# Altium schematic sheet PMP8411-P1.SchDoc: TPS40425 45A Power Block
size 431 x 279 mm; VersionControl_RevNumber: REV B; Date: Not shown in title block; ApprovedBy: Not shown in title block; CheckedBy: Not shown in title block; Author: Not shown in title block; CompanyName: Not shown in title block; DrawnBy: Tiger Zhou; Organization: Not shown in title block; Address1: Not shown in title block; Address2: Not shown in title block; Address3: Not shown in title block; Address4: Not shown in title block; DocumentNumber: 1; Revision: Use project parameter SCH_Rev; SheetNumber: 1; SheetTotal: 3; PageSetup: Record=PageOptions¦CenterHorizontal=True¦CenterVertical=True¦PrintScale=0.64¦XCorrection=1.00¦YCorrection=1.00¦PrintKind=0¦BorderSize=5000000¦LeftOffset=0¦BottomOffset=0¦Orientation=2¦PaperLength=1000¦PaperWidth=1000¦Scale=100¦PaperSource=15¦PrintQuality=600¦MediaType=1¦DitherType=10¦PrintScaleMode=1¦PaperKind=Letter
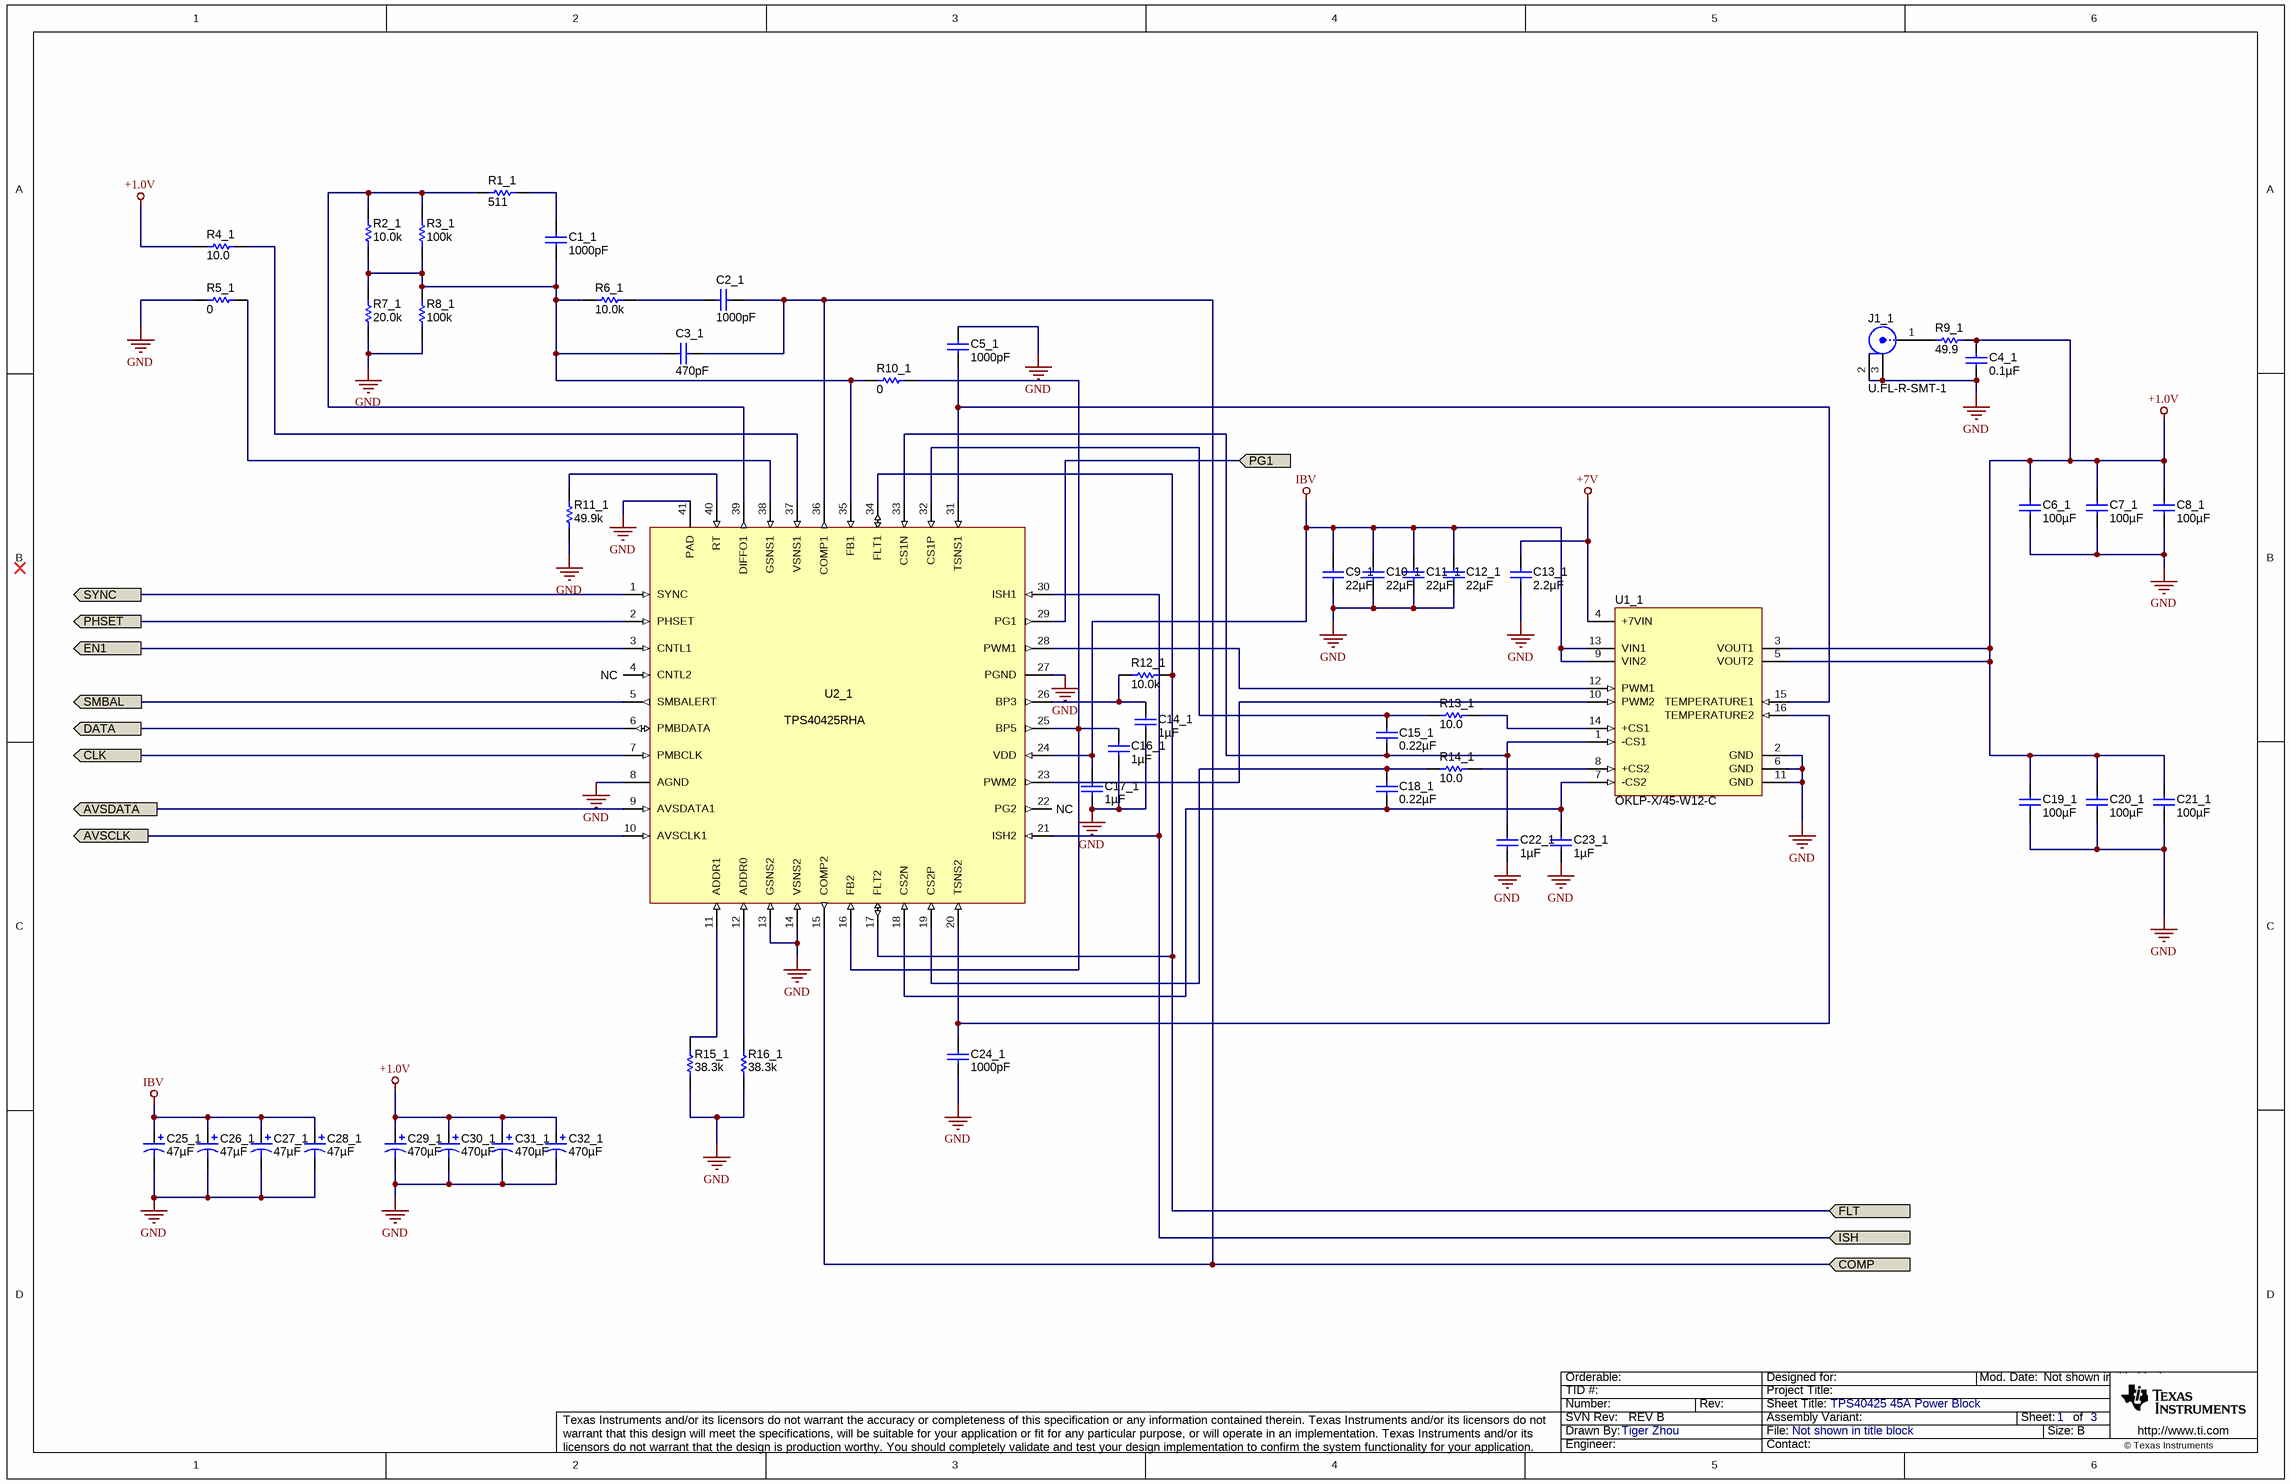
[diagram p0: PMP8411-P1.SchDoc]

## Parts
C1_1  ValueDisplayed: 1000pF  [0402S]  (hidden comment: C1005C0G1E102J)
C2_1  ValueDisplayed: 1000pF  [0402S]  (hidden comment: C1005C0G1E102J)
C3_1  ValueDisplayed: 470pF  [0402S]  (hidden comment: C1005C0G1H471J)
C4_1  ValueDisplayed: 0.1µF  [0402S]  (hidden comment: C1005X7R1H104K)
C5_1  ValueDisplayed: 1000pF  [0402S]  (hidden comment: C1005C0G1E102J)
C6_1  ValueDisplayed: 100µF  [1210]  (hidden comment: GRM32EC80J107ME20L)
C7_1  ValueDisplayed: 100µF  [1210]  (hidden comment: GRM32EC80J107ME20L)
C8_1  ValueDisplayed: 100µF  [1210]  (hidden comment: GRM32EC80J107ME20L)
C9_1  ValueDisplayed: 22µF  [1210]  (hidden comment: GRM32ER61C226KE20L)
C10_1  ValueDisplayed: 22µF  [1210]  (hidden comment: GRM32ER61C226KE20L)
C11_1  ValueDisplayed: 22µF  [1210]  (hidden comment: GRM32ER61C226KE20L)
C12_1  ValueDisplayed: 22µF  [1210]  (hidden comment: GRM32ER61C226KE20L)
C13_1  ValueDisplayed: 2.2µF  [0603S]  (hidden comment: GRM188R61C225KAAD)
C14_1  ValueDisplayed: 1µF  [0603S]  (hidden comment: C1608X5R1E105K080AC)
C15_1  ValueDisplayed: 0.22µF  [0402S]  (hidden comment: C1005X7R1C224K050BC)
C16_1  ValueDisplayed: 1µF  [0603S]  (hidden comment: C1608X5R1E105K080AC)
C17_1  ValueDisplayed: 1µF  [0603S]  (hidden comment: C1608X5R1E105K080AC)
C18_1  ValueDisplayed: 0.22µF  [0402S]  (hidden comment: C1005X7R1C224K050BC)
C19_1  ValueDisplayed: 100µF  [1210]  (hidden comment: GRM32EC80J107ME20L)
C20_1  ValueDisplayed: 100µF  [1210]  (hidden comment: GRM32EC80J107ME20L)
C21_1  ValueDisplayed: 100µF  [1210]  (hidden comment: GRM32EC80J107ME20L)
C22_1  ValueDisplayed: 1µF  [0402S]  (hidden comment: C1005X5R0J105M)
C23_1  ValueDisplayed: 1µF  [0402S]  (hidden comment: C1005X5R0J105M)
C24_1  ValueDisplayed: 1000pF  [0402S]  (hidden comment: C1005C0G1E102J)
C25_1  ValueDisplayed: 47µF  [7343-31]  (hidden comment: TPSD476M016R0080)
C26_1  ValueDisplayed: 47µF  [7343-31]  (hidden comment: TPSD476M016R0080)
C27_1  ValueDisplayed: 47µF  [7343-31]  (hidden comment: TPSD476M016R0080)
C28_1  ValueDisplayed: 47µF  [7343-31]  (hidden comment: TPSD476M016R0080)
C29_1  ValueDisplayed: 470µF  [CAPSMT_6_D3L]  (hidden comment: 4TPE470MAL)
C30_1  ValueDisplayed: 470µF  [CAPSMT_6_D3L]  (hidden comment: 4TPE470MAL)
C31_1  ValueDisplayed: 470µF  [CAPSMT_6_D3L]  (hidden comment: 4TPE470MAL)
C32_1  ValueDisplayed: 470µF  [CAPSMT_6_D3L]  (hidden comment: 4TPE470MAL)
J1_1  U.FL-R-SMT-1  [CONN_UFL-R-SMT-1]
R1_1  ValueDisplayed: 511  [0402S]  (hidden comment: CRCW0402511RFKED)
R2_1  ValueDisplayed: 10.0k  [0402S]  (hidden comment: PCF0402-12-10KBT1)
R3_1  ValueDisplayed: 100k  [0402S]  (hidden comment: CRCW0402100KFKED)
R4_1  ValueDisplayed: 10.0  [0402S]  (hidden comment: CRCW040210R0FKED)
R5_1  ValueDisplayed: 0  [0402S]  (hidden comment: ERJ-2GE0R00X)
R6_1  ValueDisplayed: 10.0k  [0402S]  (hidden comment: CRCW040210K0FKED)
R7_1  ValueDisplayed: 20.0k  [0402S]  (hidden comment: CRCW040220K0FKED)
R8_1  ValueDisplayed: 100k  [0402S]  (hidden comment: CRCW0402100KFKED)
R9_1  ValueDisplayed: 49.9  [0402S]  (hidden comment: CRCW040249R9FKED)
R10_1  ValueDisplayed: 0  [0402S]  (hidden comment: ERJ-2GE0R00X)
R11_1  ValueDisplayed: 49.9k  [0402S]  (hidden comment: CRCW040249K9FKED)
R12_1  ValueDisplayed: 10.0k  [0402S]  (hidden comment: PCF0402-12-10KBT1)
R13_1  ValueDisplayed: 10.0  [0402S]  (hidden comment: CRCW040210R0FKED)
R14_1  ValueDisplayed: 10.0  [0402S]  (hidden comment: CRCW040210R0FKED)
R15_1  ValueDisplayed: 38.3k  [0402S]  (hidden comment: CRCW040238K3FKED)
R16_1  ValueDisplayed: 38.3k  [0402S]  (hidden comment: CRCW040238K3FKED)
U1_1  OKLP-X/45-W12-C  [OKLP-X_45-W12-C]
U2_1  TPS40425RHA  [RHA0040B]

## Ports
AVSCLK, AVSDATA, CLK, COMP, DATA, EN1, FLT, ISH, PG1, PHSET, SMBAL, SYNC

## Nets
+1.0V: C4_1.1 C6_1.1 C7_1.1 C8_1.1 C19_1.1 C20_1.1 C21_1.1 C29_1.1(+) C30_1.1(+) C31_1.1(+) C32_1.1(+) R4_1.1 R9_1.2 U1_1.3(VOUT1) U1_1.5(VOUT2)
+7V: C13_1.1 U1_1.4(+7VIN)
GND: C4_1.2 C5_1.1 C6_1.2 C7_1.2 C8_1.2 C9_1.2 C10_1.2 C11_1.2 C12_1.2 C13_1.2 C14_1.2 C16_1.2 C17_1.2 C19_1.2 C20_1.2 C21_1.2 C22_1.2 C23_1.2 C24_1.2 C25_1.2(-) C26_1.2(-) C27_1.2(-) C28_1.2(-) C29_1.2(-) C30_1.2(-) C31_1.2(-) C32_1.2(-) J1_1.2 J1_1.3 R5_1.1 R7_1.1 R8_1.1 R11_1.1 R15_1.1 R16_1.1 U1_1.2(GND) U1_1.6(GND) U1_1.11(GND) U2_1.8(AGND) U2_1.13(GSNS2) U2_1.14(VSNS2) U2_1.27(PGND) U2_1.41(PAD)
IBV: C9_1.1 C10_1.1 C11_1.1 C12_1.1 C17_1.1 C25_1.1(+) C26_1.1(+) C27_1.1(+) C28_1.1(+) U1_1.9(VIN2) U1_1.13(VIN1) U2_1.24(VDD)
AVSCLK: U2_1.10(AVSCLK1) ; port AVSCLK
AVSDATA: U2_1.9(AVSDATA1) ; port AVSDATA
CLK: U2_1.7(PMBCLK) ; port CLK
COMP: C2_1.1 C3_1.1 U2_1.15(COMP2) U2_1.36(COMP1) ; port COMP
DATA: U2_1.6(PMBDATA) ; port DATA
EN1: U2_1.3(CNTL1) ; port EN1
FLT: R12_1.1 U2_1.17(FLT2) U2_1.34(FLT1) ; port FLT
ISH: U2_1.21(ISH2) U2_1.30(ISH1) ; port ISH
PG1: U2_1.29(PG1) ; port PG1
PHSET: U2_1.2(PHSET) ; port PHSET
SMBAL: U2_1.5(SMBALERT) ; port SMBAL
SYNC: U2_1.1(SYNC) ; port SYNC
NetC1_1_1: C1_1.1 R1_1.2
NetC1_1_2: C1_1.2 C3_1.2 R2_1.1 R3_1.1 R6_1.1 R7_1.2 R8_1.2 R10_1.1 U2_1.35(FB1)
NetC2_1_2: C2_1.2 R6_1.2
NetC5_1_2: C5_1.2 U1_1.15(TEMPERATURE1) U2_1.31(TSNS1)
NetC14_1_1: C14_1.1 R12_1.2 U2_1.26(BP3)
NetC15_1_1: C15_1.1 R13_1.1 U2_1.32(CS1P)
NetC15_1_2: C15_1.2 C22_1.1 U1_1.1(-CS1) U2_1.33(CS1N)
NetC16_1_1: C16_1.1 R10_1.2 U2_1.16(FB2) U2_1.25(BP5)
NetC18_1_1: C18_1.1 R14_1.1 U2_1.19(CS2P)
NetC18_1_2: C18_1.2 C23_1.1 U1_1.7(-CS2) U2_1.18(CS2N)
NetC24_1_1: C24_1.1 U1_1.16(TEMPERATURE2) U2_1.20(TSNS2)
NetJ1_1_1: J1_1.1 R9_1.1
NetR1_1_1: R1_1.1 R2_1.2 R3_1.2 U2_1.39(DIFFO1)
NetR4_1_2: R4_1.2 U2_1.37(VSNS1)
NetR5_1_2: R5_1.2 U2_1.38(GSNS1)
NetR11_1_2: R11_1.2 U2_1.40(RT)
NetR13_1_2: R13_1.2 U1_1.14(+CS1)
NetR14_1_2: R14_1.2 U1_1.8(+CS2)
NetR15_1_2: R15_1.2 U2_1.11(ADDR1)
NetR16_1_2: R16_1.2 U2_1.12(ADDR0)
NetU1_1_10: U1_1.10(PWM2) U2_1.23(PWM2)
NetU1_1_12: U1_1.12(PWM1) U2_1.28(PWM1)

Not connected (* = marked no-connect by the designer): U2_1 4(CNTL2) 22(PG2)

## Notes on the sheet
- (near U2_1) NC
- NC

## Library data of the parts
C1_1 C2_1 C5_1 C24_1 = C1005C0G1E102J: CAP, CERM, 1000 pF, 25 V, +/- 5%, C0G/NP0, 0402; Manufacturer: TDK; Polarized: N; CompType: Capacitor; Value: 1000pF; U/M: EA; Cap_F: 0.000000001; Tolerance_%: 5; Value1: Unknown; VDC_V: 25; Value2: 25V; TaMin_C: -55; TaMax_C: 125; Cap_Case: 0402
C3_1 = C1005C0G1H471J: CAP, CERM, 470 pF, 50 V, +/- 5%, C0G/NP0, 0402; Manufacturer: TDK; Polarized: N; CompType: Capacitor; Value: 470pF; U/M: EA; Cap_F: 0.00000000047; Tolerance_%: 5; ESR_ohm: 0.0788; Value1: 0.0788 ohm; VDC_V: 50; Value2: 50V; TaMin_C: -55; TaMax_C: 125; Cap_Case: 0402
C4_1 = C1005X7R1H104K: CAP, CERM, 0.1 µF, 50 V, +/- 10%, C0G/NP0, 0402; Manufacturer: TDK; Polarized: N; CompType: Capacitor; Value: 0.1uF; U/M: EA; Cap_F: 0.0000001; Tolerance_%: 10; Value1: Unknown; VDC_V: 50; Value2: 50V; TaMin_C: -55; TaMax_C: 125; Cap_Case: 0402
C6_1 C7_1 C8_1 C19_1 C20_1 C21_1 = GRM32EC80J107ME20L: CAP, CERM, 100 µF, 6.3 V, +/- 20%, X6S, 1210; Manufacturer: MuRata; Polarized: N; CompType: Capacitor; Value: 100uF; U/M: EA; Cap_F: 0.0001; Tolerance_%: 20; Value1: Unknown; VDC_V: 6.3; Value2: 6.3V; TaMin_C: -55; TaMax_C: 105
C9_1 C10_1 C11_1 C12_1 = GRM32ER61C226KE20L: CAP, CERM, 22 µF, 16 V, +/- 10%, X5R, 1210; Manufacturer: MuRata; Polarized: N; CompType: Capacitor; Value: 22uF; U/M: EA; Cap_F: 0.000022; Tolerance_%: 10; ESR_ohm: 0.002; Value1: 0.002 ohm; VDC_V: 16; Value2: 16V; IRMS_A: 3.68; TaMin_C: -55; TaMax_C: 85
C13_1 = GRM188R61C225KAAD: CAP, CERM, 2.2 µF, 16 V, +/- 10%, X5R, 0603; Manufacturer: MuRata; Polarized: N; CompType: Capacitor; Value: 2.2uF; U/M: EA; Cap_F: 0.0000022; Tolerance_%: 10; Value1: Unknown; VDC_V: 16; Value2: 16V; TaMin_C: -55; TaMax_C: 85; Cap_Case: 0603
C14_1 C16_1 C17_1 = C1608X5R1E105K080AC: CAP, CERM, 1 µF, 25 V, +/- 10%, X5R, 0603; Manufacturer: TDK; Polarized: N; CompType: Capacitor; Value: 1uF; U/M: EA; Cap_F: 0.000001; Tolerance_%: 10; Value1: Unknown; VDC_V: 25; Value2: 25V; TaMin_C: -55; TaMax_C: 85; Cap_Case: 0603
C15_1 C18_1 = C1005X7R1C224K050BC: CAP, CERM, 0.22 µF, 16 V, +/- 10%, X7R, 0402; Manufacturer: TDK; Polarized: N; CompType: Capacitor; Value: 0.22uF; U/M: EA; Cap_F: 0.00000022; Tolerance_%: 10; Value1: Unknown; VDC_V: 16; Value2: 16V; TaMin_C: -55; TaMax_C: 125; Cap_Case: 0402
C22_1 C23_1 = C1005X5R0J105M: CAP, CERM, 1 µF, 6.3 V, +/- 20%, X5R, 0402; Manufacturer: TDK; Polarized: N; CompType: Capacitor; Value: 1uF; U/M: EA; Cap_F: 0.000001; Tolerance_%: 20; ESR_ohm: 0.0079; Value1: 0.0079 ohm; VDC_V: 6.3; Value2: 6.3V; TaMin_C: -55; TaMax_C: 85; Cap_Case: 0402
C25_1 C26_1 C27_1 C28_1 = TPSD476M016R0080: CAP, TA, 47 µF, 16 V, +/- 20%, 0.08 ohm, SMD; Manufacturer: AVX; Polarized: Y; CompType: Capacitor; Value: 47uF; U/M: EA; Cap_F: 0.000047; Tolerance_%: 20; VDC_V: 16; Value2: 16V; ESR_ohm: 0.08; IRMS_A: 1.232; TaMin_C: -55; TaMax_C: 125; Cap_Case: D
C29_1 C30_1 C31_1 C32_1 = 4TPE470MAL: CAP, TA, 470 µF, 4 V, +/- 20%, 0.01 ohm, SMD; Manufacturer: Panasonic; Polarized: Y; CompType: Capacitor; Value: 470uF; U/M: EA; Cap_F: 0.00047; Tolerance_%: 20; VDC_V: 4; Value2: 4V; ESR_ohm: 0.01; IRMS_A: 4.4; TaMin_C: -55; TaMax_C: 105; Cap_Case: D3L
J1_1 = U.FL-R-SMT-1: Connector, Ultra-Mini Coaxial, SMD; Manufacturer: Hirose Electric Co. Ltd.; SymbolCreator: a0412235; U/M: EA
R1_1 = CRCW0402511RFKED: RES, 511, 1%, 0.063 W, 0402; Manufacturer: Vishay-Dale; CompType: Resistor; Value: 511; Value_Code: 511R; Tolerance_%: 1; Power_W: 0.063; Value2: 0.063W; VDC_V: 50; TempCo: 100 ppm/C; EIA_Code: E96; U/M: EA
R2_1 R12_1 = PCF0402-12-10KBT1: RES, 10.0 k, 0.1%, 0.063 W, 0402; Manufacturer: TT Electronics/IRC; CompType: Resistor; Value: 10.0k; Res_ohm: 10000; Value_Code: 10k0; Tolerance_%: 0.1; Power_W: 0.063; Value2: 0.063W; VDC_V: 25; TempCo: 10 ppm/C; EIA_Code: E192; U/M: EA
R3_1 R8_1 = CRCW0402100KFKED: RES, 100 k, 1%, 0.063 W, 0402; Manufacturer: Vishay-Dale; CompType: Resistor; Value: 100k; Res_ohm: 100000; Tolerance_%: 1; Power_W: 0.063; Value2: 0.063W; VDC_V: 50; TempCo: 100 ppm/C; EIA_Code: E96; U/M: EA
R4_1 R13_1 R14_1 = CRCW040210R0FKED: RES, 10.0, 1%, 0.063 W, 0402; Manufacturer: Vishay-Dale; CompType: Resistor; Value: 10.0; Res_ohm: 10; Value_Code: 10R0; Tolerance_%: 1; Power_W: 0.063; Value2: 0.063W; VDC_V: 50; TempCo: 100 ppm/C; EIA_Code: E96; U/M: EA
R5_1 R10_1 = ERJ-2GE0R00X: RES, 0, 5%, 0.063 W, 0402; Manufacturer: Panasonic; CompType: Resistor; Value: 0; Value_Code: 0000; Tolerance_%: 5; Power_W: 0.063; Value2: 0.063W; VDC_V: 50; TempCo: 600 ppm/C; EIA_Code: E24; U/M: EA
R6_1 = CRCW040210K0FKED: RES, 10.0 k, 1%, 0.063 W, 0402; Manufacturer: Vishay-Dale; CompType: Resistor; Value: 10.0k; Res_ohm: 10000; Value_Code: 10k0; Tolerance_%: 1; Power_W: 0.063; Value2: 0.063W; VDC_V: 50; TempCo: 100 ppm/C; EIA_Code: E96; U/M: EA
R7_1 = CRCW040220K0FKED: RES, 20.0 k, 1%, 0.063 W, 0402; Manufacturer: Vishay-Dale; CompType: Resistor; Value: 20.0k; Res_ohm: 20000; Value_Code: 20k0; Tolerance_%: 1; Power_W: 0.063; Value2: 0.063W; VDC_V: 50; TempCo: 100 ppm/C; EIA_Code: E96; U/M: EA
R9_1 = CRCW040249R9FKED: RES, 49.9, 1%, 0.063 W, 0402; Manufacturer: Vishay-Dale; CompType: Resistor; Value: 49.9; Value_Code: 49R9; Tolerance_%: 1; Power_W: 0.063; Value2: 0.063W; VDC_V: 50; TempCo: 100 ppm/C; EIA_Code: E96; U/M: EA
R11_1 = CRCW040249K9FKED: RES, 49.9 k, 1%, 0.063 W, 0402; Manufacturer: Vishay-Dale; CompType: Resistor; Value: 49.9k; Res_ohm: 49900; Value_Code: 49k9; Tolerance_%: 1; Power_W: 0.063; Value2: 0.063W; VDC_V: 50; TempCo: 100 ppm/C; EIA_Code: E96; U/M: EA
R15_1 R16_1 = CRCW040238K3FKED: RES, 38.3 k, 1%, 0.063 W, 0402; Manufacturer: Vishay-Dale; CompType: Resistor; Value: 38.3k; Res_ohm: 38300; Value_Code: 38k3; Tolerance_%: 1; Power_W: 0.063; Value2: 0.063W; VDC_V: 50; TempCo: 100 ppm/C; EIA_Code: E96; U/M: EA
U1_1 = OKLP-X/45-W12-C: 45A Power Block Non-Isolated DC/DC Converter, SMD, Body 25.4 x 12.7 mm; Manufacturer: MuRata; SymbolCreator: Altium
U2_1 = TPS40425RHA: Dual output, 2-Phase, Stackable PMBUS Synchronous Buck Driverless Controller with AVS Bus, RHA0040B; Alternate Manufacturer: None; Manufacturer: Texas Instruments; SymbolCreator: a0799628; CompType: IC; U/M: EA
